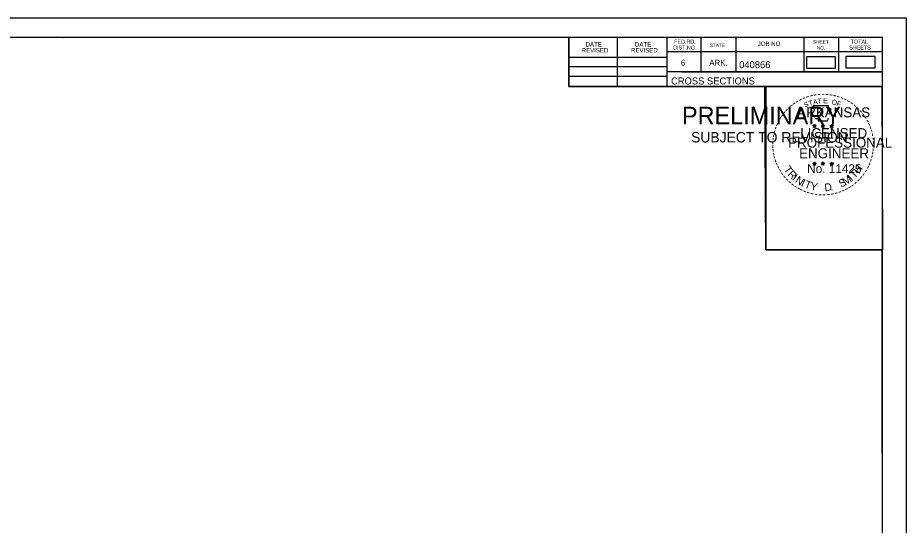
# Model space of a CAD drawing. Extents: x 1370565 to 1374448, y 301010 to 304637.
# Drawn here: x 1370720.4 to 1370898, y 301122.3 to 301223.8 of the extents above; entities that cross this region are included whole.
import ezdxf

# ---------------------------------------------------------------- set-up
doc = ezdxf.new("R2010")
doc.units = 0
for name, color, linetype in [('Default', 7, 'Continuous'), ('R_Border', 7, 'Continuous'), ('R_Border PE', 7, 'Continuous'), ('R_Border Prem', 7, 'Continuous'), ('R_Drive', 7, 'Continuous'), ('R_No Plot', 7, 'Continuous')]:
    doc.layers.add(name, color=color, linetype=linetype)

msp = doc.modelspace()

# ---------------------------------------------------------------- linework, layer by layer
at = {"layer": 'Default'}
msp.add_lwpolyline([(1370878.02, 301213.72), (1370883.85, 301213.72), (1370883.85, 301216.03), (1370878.02, 301216.03)], close=True, dxfattribs=at)
at = {"layer": 'R_Border'}
for p, q in [((1370577.03, 301219.94), (1370893.21, 301219.94)), ((1370729.55, 301219.68), (1370729.55, 301219.68)), ((1370729.55, 301219.68), (1370729.55, 301219.68)), ((1370830.57, 301210.06), (1370830.57, 301219.94)), ((1370840.25, 301210.06), (1370840.25, 301219.94)), ((1370850.11, 301219.94), (1370850.11, 301210.06)), ((1370856.95, 301219.94), (1370856.95, 301213)), ((1370863.89, 301219.94), (1370863.89, 301213)), ((1370877.47, 301219.94), (1370877.47, 301213)), ((1370884.41, 301219.94), (1370884.41, 301213)), ((1370893.21, 301014.48), (1370893.21, 301219.94)), ((1370893.21, 301217), (1370850.11, 301217)), ((1370893.21, 301217.02), (1370893.21, 301217.02)), ((1370830.57, 301215.92), (1370850.11, 301215.92)), ((1370830.57, 301214.06), (1370850.11, 301214.06)), ((1370830.57, 301212.12), (1370850.11, 301212.12)), ((1370893.21, 301213), (1370850.11, 301213)), ((1370853.07, 301213), (1370893.21, 301213)), ((1370893.21, 301210.06), (1370830.57, 301210.06))]:
    msp.add_line(p, q, dxfattribs=at)
at = {"layer": 'R_Border PE'}
for p, q in [((1370879.64, 301202.56), (1370879.6, 301202.31)), ((1370879.64, 301202.2), (1370879.64, 301202.56)), ((1370879.64, 301202.56), (1370879.69, 301202.31)), ((1370881.31, 301202.56), (1370881.27, 301202.31)), ((1370881.31, 301202.2), (1370881.31, 301202.56)), ((1370881.31, 301202.56), (1370881.36, 301202.31)), ((1370883.07, 301202.55), (1370883.03, 301202.3)), ((1370883.07, 301202.19), (1370883.07, 301202.55)), ((1370883.07, 301202.55), (1370883.12, 301202.3)), ((1370879.29, 301202.31), (1370879.64, 301202.2)), ((1370879.29, 301202.31), (1370879.54, 301202.27)), ((1370879.29, 301202.31), (1370879.53, 301202.19)), ((1370879.42, 301201.9), (1370879.64, 301202.2)), ((1370879.42, 301201.9), (1370879.55, 301202.15)), ((1370879.42, 301201.9), (1370879.64, 301202.12)), ((1370879.99, 301202.31), (1370879.64, 301202.2)), ((1370879.85, 301201.9), (1370879.64, 301202.2)), ((1370879.85, 301201.9), (1370879.64, 301202.12)), ((1370879.99, 301202.31), (1370879.7, 301202.26)), ((1370879.85, 301201.9), (1370879.72, 301202.19)), ((1370879.99, 301202.31), (1370879.78, 301202.21)), ((1370880.96, 301202.31), (1370881.31, 301202.2)), ((1370880.96, 301202.31), (1370881.21, 301202.27)), ((1370880.96, 301202.31), (1370881.2, 301202.19)), ((1370881.09, 301201.9), (1370881.31, 301202.2)), ((1370881.09, 301201.9), (1370881.22, 301202.15)), ((1370881.09, 301201.9), (1370881.31, 301202.12)), ((1370881.66, 301202.31), (1370881.31, 301202.2)), ((1370881.52, 301201.9), (1370881.31, 301202.2)), ((1370881.52, 301201.9), (1370881.31, 301202.12)), ((1370881.66, 301202.31), (1370881.37, 301202.26)), ((1370881.52, 301201.9), (1370881.39, 301202.19)), ((1370881.66, 301202.31), (1370881.45, 301202.21)), ((1370882.72, 301202.3), (1370883.07, 301202.19)), ((1370882.72, 301202.3), (1370882.98, 301202.25)), ((1370882.72, 301202.3), (1370882.96, 301202.18)), ((1370882.86, 301201.89), (1370883.07, 301202.19)), ((1370882.86, 301201.89), (1370882.98, 301202.13)), ((1370882.86, 301201.89), (1370883.07, 301202.11)), ((1370883.42, 301202.3), (1370883.07, 301202.19)), ((1370883.29, 301201.89), (1370883.07, 301202.19)), ((1370883.29, 301201.89), (1370883.07, 301202.1)), ((1370883.42, 301202.3), (1370883.13, 301202.25)), ((1370883.29, 301201.89), (1370883.15, 301202.18)), ((1370883.42, 301202.3), (1370883.22, 301202.2)), ((1370879.29, 301194.74), (1370879.64, 301194.63)), ((1370879.29, 301194.74), (1370879.54, 301194.69)), ((1370879.29, 301194.74), (1370879.52, 301194.62)), ((1370879.42, 301194.33), (1370879.64, 301194.63)), ((1370879.42, 301194.33), (1370879.55, 301194.57)), ((1370879.42, 301194.33), (1370879.63, 301194.55)), ((1370879.64, 301194.99), (1370879.59, 301194.74)), ((1370879.85, 301194.33), (1370879.63, 301194.54)), ((1370879.64, 301194.63), (1370879.64, 301194.99)), ((1370879.64, 301194.99), (1370879.68, 301194.74)), ((1370879.98, 301194.74), (1370879.64, 301194.63)), ((1370879.85, 301194.33), (1370879.64, 301194.63)), ((1370879.98, 301194.74), (1370879.7, 301194.69)), ((1370879.85, 301194.33), (1370879.71, 301194.62)), ((1370879.98, 301194.74), (1370879.78, 301194.64)), ((1370880.96, 301194.74), (1370881.3, 301194.63)), ((1370880.96, 301194.74), (1370881.21, 301194.69)), ((1370880.96, 301194.74), (1370881.19, 301194.62)), ((1370881.09, 301194.33), (1370881.3, 301194.63)), ((1370881.09, 301194.33), (1370881.21, 301194.57)), ((1370881.09, 301194.33), (1370881.3, 301194.55)), ((1370881.3, 301194.99), (1370881.26, 301194.74)), ((1370881.3, 301194.63), (1370881.3, 301194.99)), ((1370881.3, 301194.99), (1370881.35, 301194.74)), ((1370881.65, 301194.74), (1370881.3, 301194.63)), ((1370881.52, 301194.33), (1370881.3, 301194.63)), ((1370881.52, 301194.33), (1370881.3, 301194.54)), ((1370881.65, 301194.74), (1370881.37, 301194.69)), ((1370881.52, 301194.33), (1370881.38, 301194.62)), ((1370881.65, 301194.74), (1370881.45, 301194.64)), ((1370882.72, 301194.73), (1370883.07, 301194.62)), ((1370882.72, 301194.73), (1370882.98, 301194.68)), ((1370882.72, 301194.73), (1370882.96, 301194.61)), ((1370882.86, 301194.32), (1370883.07, 301194.62)), ((1370882.86, 301194.32), (1370882.98, 301194.56)), ((1370882.86, 301194.32), (1370883.07, 301194.54)), ((1370883.07, 301194.98), (1370883.03, 301194.73)), ((1370883.07, 301194.62), (1370883.07, 301194.98)), ((1370883.07, 301194.98), (1370883.12, 301194.73)), ((1370883.42, 301194.73), (1370883.07, 301194.62)), ((1370883.28, 301194.32), (1370883.07, 301194.62)), ((1370883.28, 301194.32), (1370883.07, 301194.53)), ((1370883.42, 301194.73), (1370883.13, 301194.68)), ((1370883.28, 301194.32), (1370883.15, 301194.61)), ((1370883.42, 301194.73), (1370883.21, 301194.63))]:
    msp.add_line(p, q, dxfattribs=at)
for points in [[(1370879.33, 301206.19), (1370879.6, 301205.36)], [(1370882.84, 301205.27), (1370882.98, 301205.55), (1370882.3, 301205.53), (1370882.45, 301206.19), (1370879.33, 301206.19)], [(1370879.64, 301202.56), (1370879.85, 301201.9), (1370879.29, 301202.31), (1370879.99, 301202.31), (1370879.42, 301201.9), (1370879.64, 301202.56)], [(1370879.82, 301203.77), (1370879.82, 301203.68), (1370880.39, 301203.66), (1370880.33, 301203.19), (1370882.2, 301203.19), (1370882.4, 301203.72)], [(1370881.31, 301202.56), (1370881.52, 301201.9), (1370880.96, 301202.31), (1370881.66, 301202.31), (1370881.09, 301201.9), (1370881.31, 301202.56)], [(1370883.07, 301202.55), (1370883.29, 301201.89), (1370882.72, 301202.3), (1370883.42, 301202.3), (1370882.86, 301201.89), (1370883.07, 301202.55)], [(1370879.64, 301194.99), (1370879.85, 301194.33), (1370879.29, 301194.74), (1370879.98, 301194.74), (1370879.42, 301194.33), (1370879.64, 301194.99)], [(1370881.3, 301194.99), (1370881.52, 301194.33), (1370880.96, 301194.74), (1370881.65, 301194.74), (1370881.09, 301194.33), (1370881.3, 301194.99)], [(1370883.07, 301194.98), (1370883.28, 301194.32), (1370882.72, 301194.73), (1370883.42, 301194.73), (1370882.86, 301194.32), (1370883.07, 301194.98)]]:
    msp.add_lwpolyline(points, dxfattribs=at)
for centre, radius in [((1370879.64, 301202.2), 0.172), ((1370879.64, 301202.2), 0.145), ((1370879.64, 301202.2), 0.116), ((1370879.64, 301202.2), 0.0991), ((1370879.64, 301202.2), 0.0747), ((1370879.64, 301202.2), 0.0495), ((1370879.64, 301202.2), 0.0296), ((1370881.31, 301202.2), 0.172), ((1370881.31, 301202.2), 0.145), ((1370881.31, 301202.2), 0.116), ((1370881.31, 301202.2), 0.0991), ((1370881.31, 301202.2), 0.0747), ((1370881.31, 301202.2), 0.0495), ((1370881.31, 301202.2), 0.0296), ((1370883.07, 301202.19), 0.172), ((1370883.07, 301202.19), 0.145), ((1370883.07, 301202.19), 0.116), ((1370883.07, 301202.19), 0.0991), ((1370883.07, 301202.19), 0.0747), ((1370883.07, 301202.19), 0.0495), ((1370883.07, 301202.19), 0.0296), ((1370879.63, 301194.63), 0.172), ((1370879.63, 301194.63), 0.145), ((1370879.63, 301194.63), 0.116), ((1370879.63, 301194.63), 0.0991), ((1370879.63, 301194.63), 0.0747), ((1370879.63, 301194.63), 0.0495), ((1370879.63, 301194.63), 0.0296), ((1370881.3, 301194.63), 0.172), ((1370881.3, 301194.63), 0.145), ((1370881.3, 301194.63), 0.116), ((1370881.3, 301194.63), 0.0991), ((1370881.3, 301194.63), 0.0747), ((1370881.3, 301194.63), 0.0495), ((1370881.3, 301194.63), 0.0296), ((1370883.07, 301194.62), 0.172), ((1370883.07, 301194.62), 0.145), ((1370883.07, 301194.62), 0.116), ((1370883.07, 301194.62), 0.0991), ((1370883.07, 301194.62), 0.0747), ((1370883.07, 301194.62), 0.0495), ((1370883.07, 301194.62), 0.0296)]:
    msp.add_circle(centre, radius, dxfattribs=at)
at = {"layer": 'R_Drive'}
msp.add_lwpolyline([(1370885.89, 301213.79), (1370891.72, 301213.79), (1370891.72, 301216.1), (1370885.89, 301216.1)], close=True, dxfattribs=at)
at = {"layer": 'R_No Plot'}
for p, q in [((1370564.63, 301223.83), (1370897.96, 301223.83)), ((1370869.24, 301187.6), (1370869.24, 301187.6))]:
    msp.add_line(p, q, dxfattribs=at)
for points in [[(1370564.62, 301223.83), (1370897.96, 301223.83), (1370897.96, 301010.49), (1370564.62, 301010.49)], [(1370810.95, 301219.94), (1370830.57, 301219.94), (1370830.57, 301210.06), (1370846.68, 301210.06), (1370869.88, 301210.06), (1370869.88, 301177.39), (1370893.09, 301177.39), (1370893.21, 301014.48), (1370577.03, 301014.48), (1370577.03, 301219.94)], [(1370869.74, 301210.06), (1370893.09, 301210.06), (1370893.23, 301177.39), (1370869.88, 301177.39)]]:
    msp.add_lwpolyline(points, close=True, dxfattribs=at)

# ---------------------------------------------------------------- texts
at = {"layer": 'R_Border'}
for s, height, p in [('DATE', 0.879, (1370833.9, 301218.07)), ('DATE', 0.879, (1370843.76, 301218.07)), ('FED.RD.', 0.782, (1370851.59, 301218.66)), ('STATE', 0.684, (1370858.71, 301217.98)), ('JOB NO.', 0.879, (1370868.29, 301218.18)), ('SHEET', 0.684, (1370879.33, 301218.66)), ('TOTAL', 0.782, (1370886.85, 301218.66)), ('REVISED', 0.879, (1370833.12, 301216.89)), ('REVISED', 0.879, (1370842.98, 301216.89)), ('DIST.NO.', 0.782, (1370851.39, 301217.48)), ('NO.', 0.684, (1370880.11, 301217.48)), ('SHEETS', 0.782, (1370886.57, 301217.48)), ('6', 1.17, (1370852.95, 301214.26)), ('ARK.', 1.172, (1370858.61, 301214.26)), ('040866', 1.4, (1370864.58, 301213.74)), ('CROSS SECTIONS', 1.4, (1370850.97, 301210.49))]:
    msp.add_text(s, height=height, rotation=360, dxfattribs=at).set_placement(p)
at = {"layer": 'R_Border PE'}
for s, height, rotation, p in [('-', 1.6, 24.3072, (1370877.45, 301207.05)), ('-', 1.6, 19.1761, (1370878.08, 301207.32)), ('-', 1.6, 13.6301, (1370878.83, 301207.56)), ('-', 1.6, 10.2193, (1370879.51, 301207.72)), ('-', 1.6, 5.8968, (1370880.24, 301207.83)), ('-', 1.6, 0.1862, (1370881.01, 301207.9)), ('-', 1.6, 357.743, (1370881.73, 301207.89)), ('-', 1.6, 352.1617, (1370882.48, 301207.83)), ('-', 1.6, 347.2049, (1370883.19, 301207.72)), ('-', 1.6, 342.3362, (1370883.83, 301207.56)), ('-', 1.6, 337.8551, (1370884.56, 301207.34)), ('-', 1.6, 42.9622, (1370874.73, 301205.17)), ('-', 1.6, 38.9507, (1370875.16, 301205.59)), ('-', 1.6, 36.2317, (1370875.64, 301205.96)), ('-', 1.6, 34.0636, (1370876.22, 301206.36)), ('-', 1.6, 28.7918, (1370876.81, 301206.73)), ('S', 1, 21.594, (1370877.69, 301205.87)), ('T', 1, 16.4036, (1370878.6, 301206.2)), ('A', 1, 11.2132, (1370879.43, 301206.45)), ('T', 1, 6.0228, (1370880.28, 301206.61)), ('E', 1, 0.8323, (1370881.38, 301206.72)), ('O', 1, 350.4515, (1370882.98, 301206.51)), ('F', 1, 340.0707, (1370883.94, 301206.29)), ('-', 1.6, 334.1211, (1370885.2, 301207.07)), ('-', 1.6, 329.6409, (1370885.77, 301206.79)), ('-', 1.6, 325.8627, (1370886.42, 301206.42)), ('-', 1.6, 320.5297, (1370887.03, 301206)), ('-', 1.6, 54.2325, (1370873.46, 301203.64)), ('-', 1.6, 50.6142, (1370873.88, 301204.21)), ('-', 1.6, 48.423, (1370874.28, 301204.69)), ('ARKANSAS', 2, 360, (1370876.18, 301203.9)), ('-', 1.6, 315.5786, (1370887.63, 301205.51)), ('-', 1.6, 309.8797, (1370888.2, 301204.96)), ('-', 1.6, 306.6522, (1370888.72, 301204.36)), ('-', 1.6, 67.7743, (1370872.57, 301201.89)), ('-', 1.6, 62.8713, (1370872.83, 301202.5)), ('-', 1.6, 58.0706, (1370873.14, 301203.11)), ('-', 1.4, 303.6753, (1370889.21, 301203.79)), ('-', 1.6, 299.6684, (1370889.53, 301203.18)), ('-', 1.6, 294.6628, (1370889.85, 301202.57)), ('-', 1.6, 75.461, (1370872.15, 301200.54)), ('-', 1.6, 72.3945, (1370872.35, 301201.26)), ('LICENSED', 2, 360, (1370876.78, 301199.75)), ('DWB', 0.01, 360, (1370879.63, 301202.19)), ('DWB', 0.01, 360, (1370881.3, 301202.19)), ('DWB', 0.01, 360, (1370883.06, 301202.18)), ('-', 1.6, 290.5728, (1370890.11, 301201.99)), ('-', 1.6, 285.1233, (1370890.34, 301201.41)), ('-', 1.6, 89.0622, (1370871.92, 301198.44)), ('-', 1.6, 85.1863, (1370871.94, 301199.14)), ('-', 1.6, 81.2013, (1370872.02, 301199.83)), ('PROFESSIONAL', 2, 360, (1370874.36, 301197.85)), ('-', 1.6, 280.5493, (1370890.54, 301200.67)), ('-', 1.6, 276.5962, (1370890.7, 301199.9)), ('-', 1.6, 274.3301, (1370890.76, 301199.18)), ('-', 1.6, 94.1959, (1370871.95, 301197.71)), ('-', 1.6, 98.9479, (1370872.03, 301197.05)), ('ENGINEER', 2, 360, (1370876.55, 301195.72)), ('-', 1.6, 263.5172, (1370890.78, 301197.88)), ('-', 1.6, 269.9407, (1370890.8, 301198.55)), ('-', 1.6, 101.7149, (1370872.16, 301196.31)), ('-', 1.6, 105.4578, (1370872.32, 301195.72)), ('-', 1.6, 109.0874, (1370872.54, 301195.09)), ('-', 1.6, 252.8681, (1370890.42, 301195.83)), ('-', 1.6, 255.7626, (1370890.6, 301196.55)), ('-', 1.6, 260.9953, (1370890.71, 301197.23)), ('-', 1.6, 114.0643, (1370872.79, 301194.49)), ('-', 1.6, 115.7289, (1370873.1, 301193.87)), ('T', 1.54, 306.0406, (1370873.4, 301193.47)), ('No. 11425', 1.757, 360, (1370878.17, 301192.77)), ('DWB', 0.01, 360, (1370879.62, 301194.62)), ('DWB', 0.01, 360, (1370881.29, 301194.62)), ('DWB', 0.01, 360, (1370883.06, 301194.61)), ('H', 1.54, 54.6088, (1370888.52, 301192.5)), ('-', 1.6, 244.6197, (1370889.93, 301194.53)), ('-', 1.6, 247.8887, (1370890.19, 301195.16)), ('-', 1.6, 120.4471, (1370873.45, 301193.29)), ('-', 1.6, 125.8934, (1370873.86, 301192.73)), ('-', 1.6, 130.7181, (1370874.32, 301192.17)), ('R', 1.54, 314.005, (1370874.16, 301192.42)), ('I', 1.54, 321.9694, (1370875.06, 301191.49)), ('N', 1.54, 326.5002, (1370875.63, 301191.01)), ('M', 1.54, 32.6563, (1370885.78, 301190.23)), ('I', 1.54, 42.1136, (1370887.06, 301191.08)), ('T', 1.54, 46.6444, (1370887.63, 301191.56)), ('-', 1.6, 231.2538, (1370888.7, 301192.56)), ('-', 1.6, 233.8452, (1370889.13, 301193.13)), ('-', 1.6, 239.0712, (1370889.54, 301193.78)), ('-', 1.6, 134.2238, (1370874.84, 301191.63)), ('-', 1.6, 138.9338, (1370875.36, 301191.16)), ('-', 1.6, 144.6463, (1370875.92, 301190.76)), ('-', 1.6, 148.0898, (1370876.48, 301190.39)), ('I', 1.54, 335.3603, (1370876.83, 301190.23)), ('T', 1.54, 339.8912, (1370877.49, 301189.9)), ('Y', 1.54, 347.8556, (1370878.71, 301189.45)), ('D', 1.54, 6.3969, (1370881.7, 301189.1)), ('S', 1.54, 26.9312, (1370884.94, 301189.83)), ('-', 1.6, 212.2491, (1370886.62, 301190.63)), ('-', 1.6, 215.7363, (1370887.15, 301191.01)), ('-', 1.6, 221.0851, (1370887.7, 301191.49)), ('-', 1.6, 225.7653, (1370888.23, 301192)), ('-', 1.6, 151.5704, (1370877.06, 301190.06)), ('-', 1.6, 154.6002, (1370877.58, 301189.82)), ('-', 1.6, 158.5612, (1370878.2, 301189.56)), ('-', 1.6, 162.7983, (1370878.89, 301189.35)), ('-', 1.6, 167.5555, (1370879.6, 301189.18)), ('-', 1.6, 173.1155, (1370880.38, 301189.07)), ('-', 1.6, 176.5183, (1370881.12, 301189.02)), ('-', 1.6, 181.5918, (1370881.87, 301189.04)), ('-', 1.6, 185.8167, (1370882.68, 301189.12)), ('-', 1.6, 191.2858, (1370883.41, 301189.25)), ('.', 1.54, 13.7642, (1370882.89, 301189.22)), ('-', 1.6, 195.4743, (1370884.14, 301189.45)), ('-', 1.6, 200.7184, (1370884.82, 301189.69)), ('-', 1.6, 204.2516, (1370885.44, 301189.96)), ('-', 1.6, 207.3568, (1370886.06, 301190.28))]:
    msp.add_text(s, height=height, rotation=rotation, dxfattribs=at).set_placement(p)
at = {"layer": 'R_Border Prem'}
for s, height, p in [('PRELIMINARY', 3.5, (1370853.16, 301202.52)), ('DWB', 0.01, (1370853.9, 301204.37)), ('SUBJECT TO REVISION', 2.0751, (1370854.97, 301198.89))]:
    msp.add_text(s, height=height, rotation=360, dxfattribs=at).set_placement(p)

doc.saveas('drawing.dxf')
